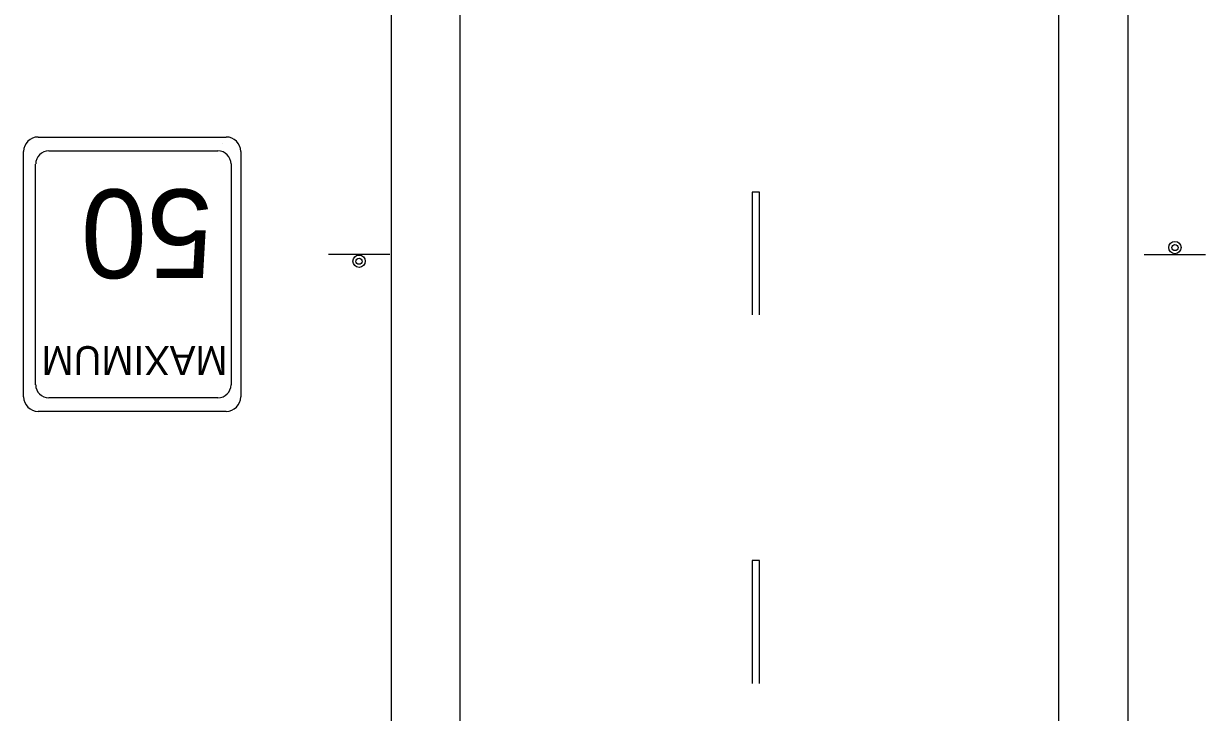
# Model space of a CAD drawing. Extents: x 1361 to 1577, y 123 to 402.
# Drawn here: x 1416.68 to 1463.24, y 293.64 to 320.75 of the extents above; entities that cross this region are included whole.
import ezdxf

# ---------------------------------------------------------------- set-up
doc = ezdxf.new("R2010")
doc.units = 0
for name, color, linetype in [('Level 10', 7, 'Continuous'), ('Level 2', 7, 'Continuous'), ('Level 44', 7, 'Continuous')]:
    doc.layers.add(name, color=color, linetype=linetype)

msp = doc.modelspace()

# ---------------------------------------------------------------- linework, layer by layer
at = {"layer": 'Level 10'}
for p, q in [((1431.161, 386.056), (1431.161, 139.681)), ((1433.872, 386.056), (1433.872, 139.681)), ((1457.451, 386.056), (1457.451, 139.681)), ((1460.18, 386.056), (1460.18, 139.681))]:
    msp.add_line(p, q, dxfattribs=at)
at = {"layer": 'Level 2'}
for p, q in [((1445.38, 314.126), (1445.38, 309.288)), ((1445.67, 314.126), (1445.38, 314.126)), ((1445.67, 309.288), (1445.67, 314.126)), ((1445.38, 299.612), (1445.38, 294.774)), ((1445.67, 299.612), (1445.38, 299.612)), ((1445.67, 294.774), (1445.67, 299.612))]:
    msp.add_line(p, q, dxfattribs=at)
at = {"layer": 'Level 44'}
for p, q in [((1417.253, 316.291), (1424.662, 316.291)), ((1416.68, 306.06), (1416.68, 315.717)), ((1417.67, 315.743), (1424.337, 315.743)), ((1424.531, 316.053), (1424.531, 316.053)), ((1425.232, 315.72), (1425.232, 315.717)), ((1425.232, 315.717), (1425.232, 306.06)), ((1417.154, 306.536), (1417.154, 315.228)), ((1424.851, 315.23), (1424.851, 315.228)), ((1424.851, 315.228), (1424.851, 306.536)), ((1431.103, 311.668), (1428.697, 311.668)), ((1460.834, 311.668), (1463.24, 311.668)), ((1424.337, 306.022), (1417.67, 306.022)), ((1424.662, 305.488), (1417.253, 305.488))]:
    msp.add_line(p, q, dxfattribs=at)
for centre, radius in [((1462.042, 311.938), 0.241), ((1462.042, 311.938), 0.12), ((1429.895, 311.399), 0.241), ((1429.895, 311.399), 0.12)]:
    msp.add_circle(centre, radius, dxfattribs=at)
for centre, radius, start, end in [((1417.253, 315.719), 0.572, 90, 180), ((1424.661, 315.719), 0.572, 360, 90), ((1417.67, 315.23), 0.514, 90, 180), ((1424.337, 315.23), 0.514, 360, 90), ((1417.67, 306.538), 0.514, 180, 270), ((1424.337, 306.538), 0.514, 270, 360), ((1417.253, 306.061), 0.572, 180, 270), ((1424.661, 306.061), 0.572, 270, 360)]:
    msp.add_arc(centre, radius, start, end, dxfattribs=at)

# ---------------------------------------------------------------- texts
for s, height, p in [('50', 3.4935, (1424.132, 314.228)), ('MAXIMUM', 1.1333, (1424.711, 308.057))]:
    msp.add_text(s, height=height, rotation=180, dxfattribs=at).set_placement(p)

doc.saveas('drawing.dxf')
